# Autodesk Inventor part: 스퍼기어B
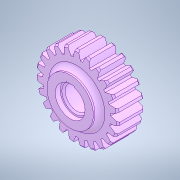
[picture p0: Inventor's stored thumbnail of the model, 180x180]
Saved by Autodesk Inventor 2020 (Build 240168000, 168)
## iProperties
Created: 2024-05
Part Number: 스퍼기어B
Material: 강철, 탄소
Document SubType Name: Modeling
Designer: oem
Density: 7.85 g/cm^3
Appearance: 기본값
Author: jhkim
Sending System: Autodesk Inventor 2025
Preprocessor: ST-DEVELOPER v20
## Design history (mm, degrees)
node "스퍼기어B1"
node "솔리드2"
node "솔리드1"
